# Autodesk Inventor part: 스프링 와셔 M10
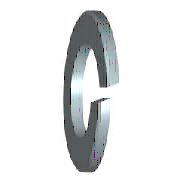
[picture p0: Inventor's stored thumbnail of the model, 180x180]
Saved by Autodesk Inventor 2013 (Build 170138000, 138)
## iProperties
IsCustomPart: 1
Created: 2012-02
Part Number: 스프링 와셔 M10
Material: 강철, 연강
Description: 스프링 와셔
Document SubType Name: Modeling
Standard: JIS B 1251
Designer: mdu-01
Standards Organization: JIS
Language: ko-KR
Size Designation: 번호 2 10
Categories: <MemberInstance><Categories><Category DisplayName="조임쇠" InternalName="e4da775c-781d-43d5-af7c-5136215cf5a6" Mnemonic="FSTN"><Category DisplayName="와셔" InternalN
Density: 1 g/cm^3
Author: mdu-01
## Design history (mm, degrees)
sketch "스케치1"
  geometry: C1 r 9.2 at (0, 0); C2 r 5.1 at (0, 0); 1 further point
  constraints: 2 centre point, 2 coincident
  dimensions: "d0" = 10.2 diameter of C2 (= SD1); "d1" = 18.4 diameter of C1 (= SD2)
extrude "본체" new body sketch "스케치1" distance "d2" = 2.5 (= SD); taper "d3" = 0 deg
sketch "스케치2"
  geometry: L1 (0, -5.1)-(0, 5.1) reference; L2 (2.5, 9.2)-(2.5, -9.2) reference; L3 (-1.2, 0)-(7.2, 0) reference; L4 (0, -0.5)-(2.5, 0.41); L5 (0, 0.5)-(2.5, 1.41)
  constraints: 4 end point, 4 point on line, 1 parallel
  dimensions: "d4" = 0.5 distance from line of L3 L4.start (= 0.2 x SD); "d5" = 0.5 distance from line of L3 L5.start (= 0.2 x SD); "d6" = 70 deg angle of L2 L4 (= FAWI)
extrude "절단부" cut sketch "스케치2" stored distance "d7" = 2.5 (= SD); taper "d8" = 0 deg
workaxis "Work Axis1"
workplane "Work Plane1"
body "Solid1"
other parameters: "SD1" = 10.2 [user parameter; used in 1 equation term], "SD2" = 18.4 [user parameter; used in 1 equation term], "SD" = 2.5 [user parameter; used in 4 equation terms], "FAWI" = 70 deg [user parameter; used in 1 equation term], "d9" = 0, "d10" = 0, "d11" = 0, "d12" = 0, "SDI" = 3.7 [user parameter]
